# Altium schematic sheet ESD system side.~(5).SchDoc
size A3; SheetNumber: 14; SheetTotal: 15
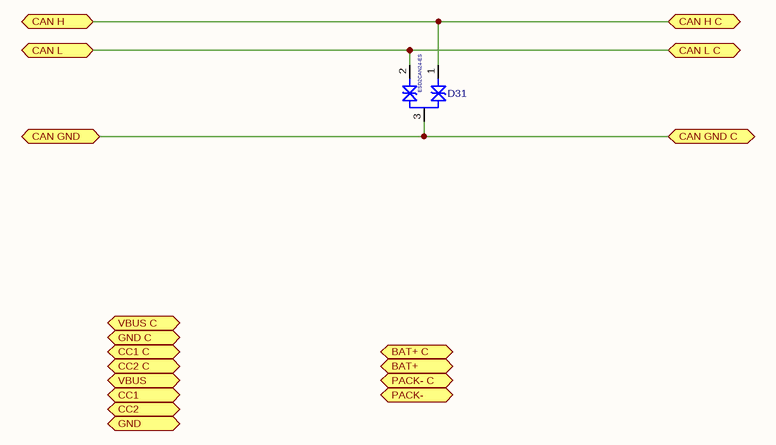
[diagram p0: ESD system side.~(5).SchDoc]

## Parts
D31  ESD2CAN24-ES  [SOT-23 123]

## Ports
BAT+ (bidir, see Arhitecture[6A], BAT+ to 5V1 STEP-DOWN[3B], BMS[1A], BQ34Z100 FUEL GAUGE[3A], BQ76952 BMS[1A], ESD battery side[5A]), BAT+ C (bidir, see Arhitecture[7A]), CAN GND (bidir, see Arhitecture[6B], BMS[8B], MCU[8B]), CAN GND C (bidir, see Arhitecture[7B]), CAN H (bidir, see Arhitecture[6B], BMS[8B], MCU[8A]), CAN H C (bidir, see Arhitecture[7B]), CAN L (bidir, see Arhitecture[6B], BMS[8B], MCU[8B]), CAN L C (bidir, see Arhitecture[7B]), CC1 (bidir, see Arhitecture[6B], CHARGER[8C]), CC1 C (bidir, see Arhitecture[7B]), CC2 (bidir, see Arhitecture[6C], CHARGER[8C]), CC2 C (bidir, see Arhitecture[7C]), GND (bidir, see Arhitecture[6C], CHARGER[8C]), GND C (bidir, see Arhitecture[7C]), PACK- (bidir, see Arhitecture[6D], BMS[8D], CHARGER[1C]), PACK- C (bidir, see Arhitecture[7D]), VBUS (bidir, see Arhitecture[6B], CHARGER[8C]), VBUS C (bidir, see Arhitecture[7B])

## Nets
CAN GND: D31.3 ; port CAN GND, port CAN GND C
CAN H: D31.1 ; port CAN H, port CAN H C
CAN L: D31.2 ; port CAN L, port CAN L C

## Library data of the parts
D31 = ESD2CAN24-ES: ESD TVS CAN; Manufacturer: ElecSuper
